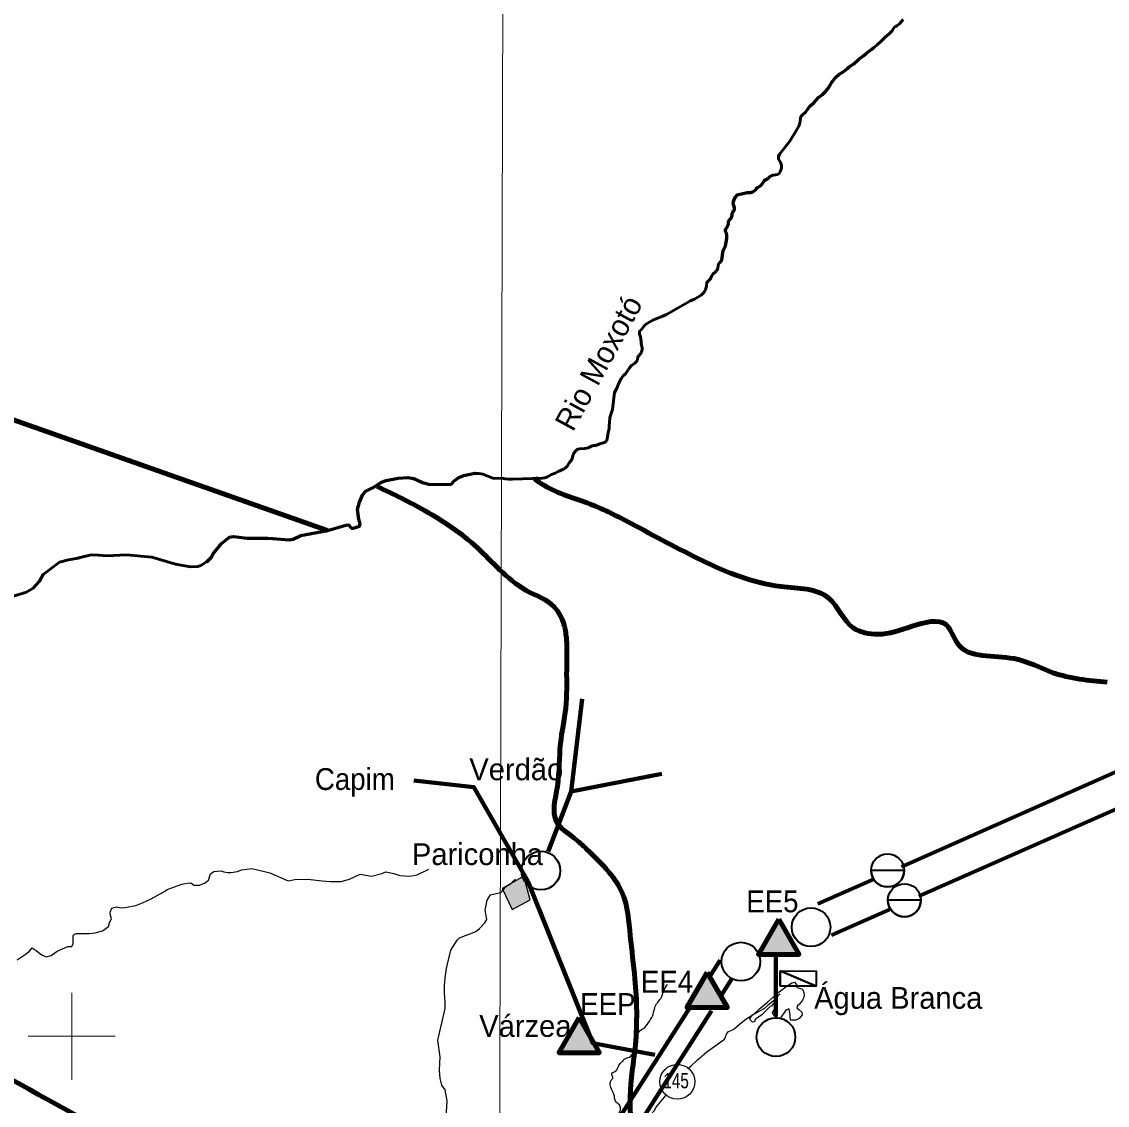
# Model space of a CAD drawing. Extents: x 553962 to 842807, y 8883888 to 9032388.
# Drawn here: x 598851 to 623792, y 8973416 to 8998304 of the extents above; entities that cross this region are included whole.
import ezdxf
from ezdxf.enums import TextEntityAlignment as Align

# ---------------------------------------------------------------- set-up
doc = ezdxf.new("R2010")
doc.units = 0
doc.header["$LTSCALE"] = 200
doc.linetypes.add('LONG_DASH_SHORT_DASH', pattern=[9.9, 6, -1.2, 1.5, -1.2])
for name, color, linetype, lineweight in [('1', 7, 'Continuous', 13), ('12', 7, 'Continuous', 25), ('2', 7, 'Continuous', 13), ('21', 7, 'Continuous', 25), ('24', 7, 'Continuous', 25), ('28', 7, 'Continuous', 40), ('41', 7, 'Continuous', 40), ('48', 7, 'Continuous', 25), ('7', 7, 'LONG_DASH_SHORT_DASH', 60), ('9', 7, 'Continuous', 90)]:
    doc.layers.add(name, color=color, linetype=linetype, lineweight=lineweight)
doc.layers.add('49', color=7, linetype='Continuous')

msp = doc.modelspace()

# ---------------------------------------------------------------- hatches: boundary and pattern name
at = {"layer": '21'}
msp.add_hatch(color=256, dxfattribs=at).paths.add_polyline_path([(609890.7, 8978396.1), (610117.7, 8977916.4), (610532.2, 8978134.8), (610383.5, 8978676.2)])
at = {"layer": '28'}
for points in [[(616243.7, 8977690.2), (616709.8, 8976882.8), (615777.6, 8976882.8)], [(614600.3, 8976468.1), (615066.4, 8975660.8), (614134.2, 8975660.8)], [(611659.2, 8975429.3), (612125.4, 8974621.9), (611193.1, 8974621.9)]]:
    msp.add_hatch(color=256, dxfattribs=at).paths.add_polyline_path(points)

# ---------------------------------------------------------------- linework, layer by layer
at = {"layer": '1'}
msp.add_lwpolyline([(609971.9, 9023551.8), (609764.7, 8949706.7), (609734.2, 8939404.4)], dxfattribs=at)
at = {"layer": '12'}
for points in [[(615222.8, 8975168.5), (615339, 8975277.8), (615490.8, 8975390.2), (615612.1, 8975473.5), (615808.6, 8975586), (615925.4, 8975649.3), (616008.4, 8975727.6), (616074.8, 8975783.8), (616145, 8975840), (616263.2, 8975966.3), (616268.5, 8975969.3), (616277.5, 8975970.4)], [(614179.1, 8974275.6), (614232, 8974325.6), (614380.4, 8974459), (614591.6, 8974640.6), (614857, 8974834.3), (614998.5, 8974937.7), (615021.7, 8974991.9), (615045, 8975053), (615091.5, 8975110.2), (615204.3, 8975158.4), (615222.8, 8975168.5)], [(612832.5, 8972676.8), (613380.5, 8973289.6), (613425.9, 8973370.8), (613657.1, 8973648.4)]]:
    msp.add_lwpolyline(points, dxfattribs=at)
at = {"layer": '2'}
for p, q in [((600000, 8974000), (600000, 8976000)), ((599000, 8975000), (601000, 8975000))]:
    msp.add_line(p, q, dxfattribs=at)
at = {"layer": '21'}
for points in [[(609890.7, 8978396.1), (610117.7, 8977916.4), (610532.2, 8978134.8), (610383.5, 8978676.2)], [(616255.9, 8976024.9), (616407.9, 8976137.7), (616530.4, 8976221), (616608.8, 8976240.7), (616653, 8976191.6), (616657.9, 8976118.1), (616770.6, 8976093.6), (616800, 8976064.1), (616819.6, 8976005.3), (616824.5, 8975941.5), (616814.7, 8975872.9), (616790.2, 8975828.8), (616721.6, 8975740.5), (616677.5, 8975701.2), (616657.9, 8975657.1), (616706.9, 8975617.9), (616770.6, 8975554.1), (616780.4, 8975495.3), (616716.7, 8975407), (616638.3, 8975367.8), (616559.8, 8975367.8), (616515.7, 8975372.7), (616496.1, 8975549.2), (616481.4, 8975622.8), (616456.9, 8975622.8), (616407.9, 8975603.2), (616349.1, 8975510), (616319.6, 8975480.6), (616304.9, 8975456.1), (616280.4, 8975426.7), (616221.6, 8975411.9), (616153, 8975461), (616113.8, 8975510), (616099, 8975549.2), (616197.1, 8975730.7), (616206.9, 8975769.9), (616187.3, 8975818.9), (616162.8, 8975809.1), (616079.4, 8975696.3), (616045.1, 8975686.5), (615853.9, 8975490.4), (615702, 8975387.4), (615687.3, 8975333.5), (615638.2, 8975323.7), (615594.1, 8975367.8), (615579.4, 8975411.9), (615643.2, 8975495.3), (615677.5, 8975514.9), (615809.8, 8975642.4), (615991.2, 8975789.5)]]:
    msp.add_lwpolyline(points, close=True, dxfattribs=at)
at = {"layer": '24'}
msp.add_line((609963.1, 8978425.2), (609985.3, 8978448.2), dxfattribs=at)
at = {"layer": '24', "lineweight": 53}
for points in [[(616275, 8994855), (616299.8, 8994916), (616306.6, 8994947), (616309.5, 8994997), (616289.9, 8995061), (616239.9, 8995143), (616235.6, 8995179), (616237.4, 8995206), (616262.8, 8995260), (616352.4, 8995378.9), (616439.6, 8995482.9), (616497.8, 8995558.9), (616654.6, 8995808.9), (616704.2, 8995904.9), (616721.4, 8995949.9), (616734.9, 8996009.9), (616742.4, 8996094.9), (616755.2, 8996130.9), (616770.5, 8996150.9), (616865.5, 8996231.9), (616968.5, 8996369.9), (617050.4, 8996439.9), (617160.7, 8996559.9), (617252.1, 8996633.9), (617320.9, 8996701.9), (617376, 8996767.9), (617466.2, 8996912.9), (617553.7, 8997026.9), (617627.5, 8997088.9), (617747.7, 8997167.8), (617821.7, 8997231.8), (617864.4, 8997264.8), (617970.3, 8997332.8), (618086, 8997441.8), (618201.6, 8997530.8), (618257.2, 8997582.8), (618380.8, 8997669.8), (618495.1, 8997763.8), (618608.2, 8997867.8), (618687.2, 8997947.8), (618784.2, 8998026.8), (618847.8, 8998091.8), (618880.8, 8998148.8), (618904.8, 8998177.8), (618927, 8998194.8), (618960.5, 8998211.8), (619017, 8998253.8), (619099.7, 8998350.8)], [(615088.6, 8993660), (615092.1, 8993720), (615153, 8993790), (615174.6, 8993852), (615175.1, 8993904), (615179, 8993921), (615187.3, 8993934), (615211.5, 8993958), (615228.8, 8993992), (615227.7, 8994030), (615203.4, 8994096), (615199.3, 8994145), (615206.1, 8994178), (615239.1, 8994264), (615295.5, 8994325), (615320, 8994336), (615520.9, 8994382), (615601.5, 8994383), (615661.9, 8994403), (615699.6, 8994431), (615734.4, 8994474), (615755.4, 8994494), (615812.3, 8994527), (615840.8, 8994550), (615864.4, 8994578), (615900.1, 8994637), (615919.4, 8994659), (615934.8, 8994670), (615988.9, 8994692), (616008.8, 8994710), (616037.3, 8994745), (616076.4, 8994766), (616108.6, 8994778), (616169.1, 8994784), (616218.9, 8994795), (616250.2, 8994821), (616275, 8994855)], [(612374.7, 8989257.2), (612410.1, 8989349.2), (612422.8, 8989393.2), (612443.9, 8989595.2), (612472.1, 8989790.2), (612521.4, 8989889.2), (612567.7, 8990001.2), (612623.5, 8990108.2), (612679.4, 8990175.2), (612720.8, 8990217.2), (612815.3, 8990351.2), (612864.4, 8990407.2), (612937.9, 8990460.2), (612974.6, 8990496.2), (612997.1, 8990536.2), (613004.6, 8990605.2), (613071.9, 8990685.2), (613099.4, 8990741.2), (613104.8, 8990769.2), (613104.8, 8990813.2), (613086.3, 8990905.2), (613085.9, 8990954.2), (613066.1, 8991064.2), (613044.7, 8991133.2), (613043.4, 8991164.2), (613047.9, 8991196.2), (613081.7, 8991228.2), (613169.8, 8991332.2), (613227.7, 8991376.2), (613365.8, 8991458.1), (613579.6, 8991541.1), (613666.1, 8991582.1), (614090.8, 8991825.1), (614218.9, 8991891.1), (614310.9, 8991932.1), (614460.7, 8992023.1), (614532.5, 8992094.1), (614543.7, 8992113.1), (614569, 8992177.1), (614582, 8992234.1), (614589.2, 8992317.1), (614668.2, 8992394.1), (614704.5, 8992469.1), (614728, 8992505.1), (614788.8, 8992558.1), (614827.1, 8992602.1), (614841.2, 8992635.1), (614852.2, 8992705.1), (614861.2, 8992733.1), (614874, 8992755.1), (614920, 8992803.1), (614934.5, 8992832.1), (614943.5, 8992879.1), (614957.9, 8993016), (614981.1, 8993081), (615017.2, 8993154), (615053.5, 8993321), (615053.4, 8993409), (615046.2, 8993436), (615020.3, 8993489), (615020.7, 8993515), (615030.5, 8993541), (615082.9, 8993633), (615082.9, 8993633), (615088.6, 8993660)], [(610812.6, 8987820.3), (610868.6, 8987825.3), (610933, 8987849.3), (611023.7, 8987905.3), (611105.7, 8987931.3), (611174.3, 8987972.3), (611295.8, 8988024.3), (611334, 8988050.3), (611392.2, 8988106.3), (611428.2, 8988171.3), (611476.2, 8988225.3), (611496.6, 8988270.3), (611519.8, 8988356.3), (611535.1, 8988392.3), (611570.6, 8988443.3), (611611.3, 8988477.3), (611633.5, 8988486.3), (611663.2, 8988493.3), (611778.5, 8988500.3), (611831.3, 8988507.2), (611867.2, 8988517.2), (611960.5, 8988564.2), (611993.5, 8988570.2), (612040.4, 8988571.2), (612135.1, 8988609.2), (612211, 8988629.2), (612253, 8988646.2), (612280.4, 8988668.2), (612294.2, 8988690.2), (612304.8, 8988723.2), (612325, 8988861.2), (612344.1, 8988963.2), (612347.8, 8989019.2), (612358.9, 8989089.2), (612362.3, 8989210.2), (612374.7, 8989257.2)], [(608722.9, 8987680.8), (608777.9, 8987747.6), (608897.1, 8987833.6), (609009.5, 8987880.2), (609264.4, 8987935.4), (609356.3, 8987924.6)], [(609356.3, 8987924.6), (609448.1, 8987913.7), (609678.6, 8987816.5)], [(606420.8, 8986668), (606473.8, 8986668.1), (606613.3, 8986714.2), (606626.1, 8986769), (606594.2, 8986880), (606564.5, 8987100.6), (606609.1, 8987266.3), (606681.2, 8987431.8), (606741, 8987512.8), (606939.6, 8987610), (607118.9, 8987727.3), (607224.8, 8987767.6), (607501, 8987816.5), (607722.2, 8987831.4), (607811.1, 8987818.7)], [(607811.1, 8987818.7), (607857.5, 8987812), (608058.1, 8987723), (608202.2, 8987682.7), (608346.4, 8987672.1), (608722.9, 8987680.8)], [(609678.6, 8987816.5), (609919.3, 8987814.4), (609966, 8987801.4), (610032.6, 8987795.3), (610127.9, 8987794.3), (610812.6, 8987820.3)], [(604502.8, 8986438.7), (604614.5, 8986437.8), (604995.5, 8986406.1), (605088.3, 8986418.9), (605266.8, 8986501.7), (605873.8, 8986618.4), (606294.7, 8986737.4), (606369.1, 8986745.7), (606420.8, 8986668)], [(603138.8, 8985934.3), (603201.3, 8985995.2), (603246.4, 8986085.3), (603439.7, 8986316.8), (603622.3, 8986468.1), (603715.8, 8986478.2), (604022, 8986442.1), (604249.4, 8986440.5), (604502.8, 8986438.7)], [(599176.5, 8985365.4), (599258.9, 8985456.2), (599344, 8985609.2), (599718.7, 8985887.4)], [(599718.7, 8985887.4), (599721.5, 8985889.5), (599926.2, 8985947.2), (600149.2, 8985983.3), (600164.2, 8985987.1)], [(600164.2, 8985987.1), (600446.9, 8986057.4), (600614.3, 8986048.6)], [(600614.3, 8986048.6), (600805.6, 8986038.6), (601260, 8986057.6), (601842, 8986004.5), (602386.1, 8985845.2), (602725.9, 8985781.5), (602895.9, 8985787.9), (602963.8, 8985811.2), (603100.1, 8985896.5), (603138.8, 8985934.3)], [(598562.6, 8985004.4), (598611, 8985091.4), (598961, 8985203.4), (599114.5, 8985297), (599176.5, 8985365.4)]]:
    msp.add_lwpolyline(points, dxfattribs=at)
at = {"layer": '24'}
for points in [[(602527.9, 8978491.8), (602650.6, 8978515.2), (602738.6, 8978522.5), (602804.6, 8978471.2), (602936.6, 8978471.2), (603068.6, 8978522.5), (603142, 8978588.6), (603186, 8978735.3), (603266.7, 8978786.7), (603347.3, 8978794), (603435.3, 8978801.4), (603494, 8978779.4), (603582, 8978764.7), (603655.3, 8978764.7), (603809.3, 8978786.7)], [(603809.3, 8978786.7), (603897.3, 8978823.4), (604022, 8978838.1), (604139.3, 8978852.8), (604271.3, 8978823.4), (604432.7, 8978786.7), (604550, 8978757.3), (604975, 8978572.4)], [(604975, 8978572.4), (605129.4, 8978603.2), (605415.4, 8978610.6), (605752.7, 8978573.9), (605943.4, 8978559.2), (606192.7, 8978559.2), (606383.4, 8978610.6), (606625.4, 8978728), (606889.4, 8978676.6), (607124.1, 8978742.7), (607219.4, 8978779.4), (607402.8, 8978742.7), (607534.8, 8978691.3), (607769.4, 8978676.6), (607938.1, 8978706), (608202.1, 8978838.1)], [(598746.2, 8976759.4), (598932.5, 8976878.8), (599027.9, 8976952.2), (599093.9, 8977032.9), (599181.9, 8976974.2), (599269.9, 8976900.8), (599328.6, 8976864.1), (599416.6, 8976827.4), (599526.6, 8976856.8), (599665.9, 8976952.2), (599907.9, 8977062.2), (600003.2, 8977062.2), (600032.6, 8977135.6), (600032.6, 8977238.3), (600032.6, 8977319.1), (600061.9, 8977348.4), (600113.2, 8977363.1), (600274.6, 8977363.1), (600399.2, 8977363.1), (600538.6, 8977377.8), (600707.2, 8977421.8), (600846.6, 8977524.5), (600868.6, 8977605.3), (600912.6, 8977708), (600890.6, 8977774), (600883.2, 8977854.8), (600919.9, 8977942.8), (601029.9, 8977972.2), (601125.3, 8977950.2), (601220.6, 8977957.5), (601469.9, 8978001.5), (601623.9, 8978067.6), (601821.9, 8978155.6), (601961.3, 8978236.3), (602115.3, 8978317.1), (602196, 8978368.4), (602527.9, 8978491.8)], [(608764.9, 8977065.1), (608854.4, 8977208), (608912.6, 8977261.5), (609281.4, 8977407.7), (609370.8, 8977473.7), (609493.8, 8977609.5), (609536.2, 8977684.1), (609500.2, 8977893.9), (609548.1, 8978125.2), (609619.8, 8978247.6), (609848.8, 8978304.7), (609863.5, 8978311.5), (609888.4, 8978332.5), (609966.3, 8978428.5)], [(609988.6, 8978451.5), (610010.3, 8978466.5), (610061.1, 8978489.5), (610086.1, 8978510.5), (610150.8, 8978570.6), (610195.3, 8978607.5)], [(608626.7, 8976624.4), (608712.1, 8976980.7), (608764.9, 8977065.1)], [(608573.2, 8975888.4), (608564.5, 8976001.3), (608562, 8976152), (608579.7, 8976343.3), (608594.9, 8976450.9), (608611.3, 8976558.6), (608626.7, 8976624.4)], [(608412.1, 8974909.8), (608578.3, 8975642.7), (608577.2, 8975782.8), (608573.2, 8975888.4)], [(607981.4, 8972045.9), (608340.3, 8972373.2), (608504, 8972626.3), (608557, 8972753.5), (608584.6, 8972880.9), (608629.2, 8973517.9), (608582.5, 8973773.1), (608506, 8973879.6), (608465.7, 8974028), (608448.7, 8974219.2), (608463.5, 8974525.1), (608412.1, 8974909.8)]]:
    msp.add_lwpolyline(points, dxfattribs=at)
for points in [[(612653, 8974423.1), (612709.6, 8974484.8), (612812.4, 8974520.8), (612910, 8974644.2), (612987.1, 8974870.5), (612997.4, 8975019.7), (613069.4, 8975138), (613167, 8975204.8), (613280.1, 8975359.1), (613341.8, 8975462), (613393.2, 8975652.3), (613454.9, 8975770.6), (613532, 8975868.3), (613609.1, 8976058.6), (613686.2, 8976187.2)], [(612667.9, 8967747.4), (612667.9, 8967790.6), (612680.2, 8967833.7), (612689.4, 8967892.3), (612701.8, 8967938.6), (612692.5, 8967987.9), (612692.5, 8968024.9), (612726.4, 8968049.6), (612775.7, 8968098.9), (612785, 8968114.3), (612741.8, 8968172.9), (612704.8, 8968231.5), (612692.5, 8968339.4), (612692.5, 8968425.8), (612738.8, 8968487.5), (612781.9, 8968533.7), (612694.2, 8968580), (612482.9, 8968630.8), (612373, 8968664.6), (612212.4, 8969002.9), (612043.3, 8969189), (611899.7, 8969349.7), (611882.8, 8969392), (612026.5, 8969392), (612187.1, 8969451.2), (612254.7, 8969544.2), (612204, 8969662.7), (612077.2, 8969984.1), (612026.5, 8970153.2), (611967.3, 8970271.6), (612018, 8970415.4), (612059.6, 8970464.8), (612178.6, 8970464.8), (612198.5, 8970524.3), (612143.9, 8970638.6), (612134, 8970737.9), (612183.6, 8970832.2), (612198.5, 8970901.7), (612173.7, 8970996.1), (612153.8, 8971095.4), (612034.7, 8971169.8), (611950.4, 8971234.4), (611811.4, 8971313.8), (611756.8, 8971358.5), (611742, 8971462.8), (611712.2, 8971557.2), (611702.3, 8971636.6), (611756.8, 8971686.2), (611801.5, 8971686.2), (611829.2, 8971666.8), (611881.3, 8971661.6), (611964.6, 8971705.9), (612040.2, 8971737.1), (612128.7, 8971752.8), (612212, 8971778.8), (612238.1, 8971812.7), (612258.9, 8971872.6), (612264.1, 8971989.9), (612258.9, 8972052.5), (612245.9, 8972091.6), (612199, 8972120.2), (612087, 8972203.6), (612029.7, 8972268.8), (611993.3, 8972341.7), (612000.3, 8972381.2), (612077.3, 8972484.1), (612113.3, 8972556.1), (612180.2, 8972607.5), (612231.6, 8972664.1), (612288.1, 8972725.8), (612318.9, 8972792.7), (612396, 8972854.4), (612426.9, 8972905.8), (612468, 8973024.1), (612498.8, 8973137.3), (612550.2, 8973199), (612601.6, 8973286.4), (612606.8, 8973368.7), (612596.5, 8973409.9), (612524.5, 8973471.6), (612478.3, 8973553.9), (612462.8, 8973646.5), (612370.3, 8973888.2), (612396, 8973991.1), (612432, 8974057.9), (612406.3, 8974140.2), (612416.6, 8974160.8), (612473.1, 8974181.4), (612555.4, 8974299.7), (612622.2, 8974397.4), (612653, 8974423.1)]]:
    msp.add_spline(points, degree=3, dxfattribs=at)
at = {"layer": '28', "lineweight": 80}
for p, q in [((611474, 8980619.7), (611727.1, 8982754)), ((619061.2, 8978891.7), (627201.1, 8982499.9)), ((619464.9, 8978215.4), (627432, 8981747)), ((617140.3, 8978040.2), (618426.7, 8978610.4)), ((617457.6, 8977325.6), (618823.9, 8977931.3)), ((614642.1, 8976353.3), (614896.2, 8976751.4)), ((616175.1, 8976842.8), (616175.1, 8975459)), ((614936.3, 8975957.7), (615176.1, 8976333.3))]:
    msp.add_line(p, q, dxfattribs=at)
at = {"layer": '28'}
for p, q in [((619125.1, 8978809.6), (618366.3, 8978809.6)), ((619511, 8978125.5), (618752.2, 8978125.5))]:
    msp.add_line(p, q, dxfattribs=at)
at = {"layer": '28', "lineweight": 80}
for points in [[(610947.2, 8979245.6), (611474, 8980619.7), (613557.9, 8981028.6)], [(610480.9, 8978566.1), (609235.2, 8980723.9), (607861.4, 8980874.2)], [(613394.2, 8974574.6), (611970.3, 8974843.5), (610480.9, 8978566.1)], [(609785.7, 8962480.2), (611783.9, 8971876.8), (614204.9, 8975668.6)], [(610282, 8962611.2), (612213.1, 8971692.7), (614696.7, 8975582.5)]]:
    msp.add_lwpolyline(points, dxfattribs=at)
at = {"layer": '28', "lineweight": 90}
for points in [[(616243.7, 8977690.2), (616709.8, 8976882.8), (615777.6, 8976882.8)], [(614600.3, 8976468.1), (615066.4, 8975660.8), (614134.2, 8975660.8)], [(611659.2, 8975429.3), (612125.4, 8974621.9), (611193.1, 8974621.9)]]:
    msp.add_lwpolyline(points, close=True, dxfattribs=at)
at = {"layer": '28'}
msp.add_lwpolyline([(616276.4, 8976502.4), (617106.2, 8976496.5), (617103.7, 8976154.6), (616274, 8976160.5)], close=True, dxfattribs=at)
for points in [[(616276.4, 8976502.4), (616274, 8976160.5), (617103.7, 8976154.6)], [(616276.4, 8976502.4), (617103.7, 8976154.6), (616276.4, 8976502.4)]]:
    msp.add_lwpolyline(points, dxfattribs=at)
for centre, radius in [((610778.9, 8978806.8), 444.4), ((618745.7, 8978809.6), 379.4), ((619131.6, 8978125.5), 379.4), ((616985.8, 8977506), 444.4), ((615374.9, 8976715.2), 444.4), ((616180.4, 8974981.6), 444.4)]:
    msp.add_circle(centre, radius, dxfattribs=at)
for centre in [(618745.7, 8978809.6), (619131.6, 8978125.5)]:
    msp.add_arc(centre, 379.4, 180, 0, dxfattribs=at)
at = {"layer": '48'}
msp.add_circle((613915.8, 8973955.5), 401.3, dxfattribs=at)
at = {"layer": '7', "lineweight": 35}
msp.add_line((610685.7, 8987847), (610687.2, 8987846.5), dxfattribs=at)
at = {"layer": '7'}
msp.add_line((603104.5, 8985900.8), (603138.8, 8985934.3), dxfattribs=at)
for points in [[(616899, 8996276.8), (616968.5, 8996369.9), (617050.4, 8996439.9), (617160.7, 8996559.9), (617252.1, 8996633.9), (617320.9, 8996701.9), (617376, 8996767.9), (617466.2, 8996912.9), (617553.7, 8997026.9), (617627.5, 8997088.9), (617747.7, 8997167.8), (617821.7, 8997231.8), (617864.4, 8997264.8), (617970.3, 8997332.8), (618086, 8997441.8), (618201.6, 8997530.8), (618257.2, 8997582.8), (618380.8, 8997669.8), (618437.7, 8997716.6)], [(615088.6, 8993660), (615092.1, 8993720), (615153, 8993790), (615174.6, 8993852), (615175.1, 8993904), (615179, 8993921), (615187.3, 8993934), (615211.5, 8993958), (615228.8, 8993992), (615227.7, 8994030), (615203.4, 8994096), (615199.3, 8994145), (615206.1, 8994178), (615239.1, 8994264), (615295.5, 8994325), (615320, 8994336), (615520.9, 8994382), (615601.5, 8994383), (615661.9, 8994403), (615699.6, 8994431), (615734.4, 8994474), (615755.4, 8994494), (615812.3, 8994527), (615840.8, 8994550), (615864.4, 8994578), (615900.1, 8994637), (615919.4, 8994659), (615934.8, 8994670), (615988.9, 8994692), (616008.8, 8994710), (616037.3, 8994745)], [(614923.2, 8992809.3), (614934.5, 8992832.1), (614943.5, 8992879.1), (614957.9, 8993016), (614981.1, 8993081), (615017.2, 8993154), (615053.5, 8993321), (615053.4, 8993409), (615046.2, 8993436), (615020.3, 8993489), (615020.7, 8993515), (615030.5, 8993541), (615082.9, 8993633), (615082.9, 8993633), (615088.6, 8993660)], [(608722.9, 8987680.8), (608777.9, 8987747.6), (608897.1, 8987833.6), (609009.5, 8987880.2), (609264.4, 8987935.4), (609347, 8987925.7)], [(606420.8, 8986668), (606473.8, 8986668.1), (606613.3, 8986714.2), (606626.1, 8986769), (606594.2, 8986880), (606564.5, 8987100.6), (606609.1, 8987266.3), (606681.2, 8987431.8), (606741, 8987512.8), (606939.6, 8987610), (607118.9, 8987727.3), (607224.8, 8987767.6), (607501, 8987816.5), (607722.2, 8987831.4), (607811.1, 8987818.7)], [(607811.1, 8987818.7), (607857.5, 8987812), (608058.1, 8987723), (608202.2, 8987682.7), (608346.4, 8987672.1), (608722.9, 8987680.8)], [(604502.8, 8986438.7), (604614.5, 8986437.8), (604995.5, 8986406.1), (605088.3, 8986418.9), (605266.8, 8986501.7), (605873.8, 8986618.4), (606294.7, 8986737.4), (606369.1, 8986745.7), (606420.8, 8986668)], [(603138.8, 8985934.3), (603201.3, 8985995.2), (603246.4, 8986085.3), (603439.7, 8986316.8), (603622.3, 8986468.1), (603715.8, 8986478.2), (604022, 8986442.1), (604249.4, 8986440.5), (604502.8, 8986438.7)]]:
    msp.add_lwpolyline(points, dxfattribs=at)
at = {"layer": '9'}
msp.add_lwpolyline([(605873.8, 8986618.4), (590956.6, 8991866.7), (589163, 9005713.7)], dxfattribs=at)
for points in [[(623791.9, 8983133), (622543.6, 8983352), (621651, 8983674.8), (620351.1, 8984020), (620094.1, 8984448.6), (619305.4, 8984417.7), (618517.6, 8984234.9), (617956.8, 8984382.8), (617392.9, 8985062.3), (616297.1, 8985333.1), (614486.7, 8985927.8), (612853, 8986777), (611908.8, 8987226), (610862.9, 8987648.9), (610631.7, 8987802.8)], [(607019.9, 8987628.8), (608117.9, 8987072.5), (609319, 8986220.3), (609831, 8985717.6), (610444.6, 8985240.9), (611083, 8984865.7), (611314.6, 8984437), (611367.4, 8984108.2), (611371.5, 8983424.7), (611351.3, 8982538.5), (611228.8, 8981727.5), (611158.3, 8980739.6), (611137.7, 8979929.4), (611547.1, 8979552.5), (611828.5, 8979301.3), (612340.6, 8978773.3), (612648.8, 8978294.5), (612832.8, 8977308.5), (612940.5, 8976321.9), (612949.5, 8974803), (612829.3, 8973612.2), (613105.4, 8971372.7), (613572.8, 8968712.3), (614200.8, 8967292.3), (614110, 8965907), (613645.9, 8964639.4)], [(592698.5, 8977198.4), (599903.5, 8973292.7), (608459.2, 8968138.2), (612674.8, 8965332.6), (616842, 8962096.4), (620005, 8958671.2), (621134, 8957974.7), (621473.4, 8956805.3), (621586.2, 8956597.5)]]:
    msp.add_spline(points, degree=3, dxfattribs=at)

# ---------------------------------------------------------------- texts
at = {"layer": '28', "width": 0.95}
for s, p in [('EE5', (615497.2, 8977849.4)), ('EE4', (613076.4, 8976004.4)), ('EEP', (611682.1, 8975492.1))]:
    msp.add_text(s, height=500, dxfattribs=at).set_placement(p)
at = {"layer": '41'}
for s, p in [('Verdão', (609135.1, 8980881.8)), ('Pariconha', (607816.3, 8978933.9)), ('Pariconha', (607816.3, 8978933.9)), ('Água Branca', (617056.5, 8975633.4)), ('Várzea', (609362.6, 8974987.3))]:
    msp.add_text(s, height=500, dxfattribs=at).set_placement(p)
at = {"layer": '41', "width": 0.95}
msp.add_text('Capim', height=500, dxfattribs=at).set_placement((605587.2, 8980658.8))
at = {"layer": '48', "width": 0.75}
msp.add_text('145', height=350, dxfattribs=at).set_placement((613885.7, 8973806.7), align=Align.CENTER)
at = {"layer": '49'}
msp.add_text('Rio Moxotó', height=500, rotation=61.364, dxfattribs=at).set_placement((612325.1, 8990347.9), align=Align.CENTER)

doc.saveas('drawing.dxf')
